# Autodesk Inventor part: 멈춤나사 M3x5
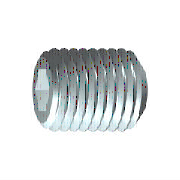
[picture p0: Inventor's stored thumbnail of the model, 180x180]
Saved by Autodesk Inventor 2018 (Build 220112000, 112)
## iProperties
Created: 2012-02
Part Number: 멈춤나사 M3x5
Material: 강철, 연강
Description: 6각 소켓 머리 없는 멈춤 나사
Document SubType Name: Modeling
Standard: KS B 1028
Designer: mduedu
Standards Organization: KS
Language: ko-KR
Size Designation: 납작점M3x5
Categories: <MemberInstance><Categories><Category DisplayName="조임쇠" InternalName="e4da775c-781d-43d5-af7c-5136215cf5a6" Mnemonic="FSTN"><Category DisplayName="볼트" InternalN
Density: 7.85 g/cm^3
Appearance: 노란색
Mass: 0.237365 g
Surface Area: 0.685518 cm^2
Volume: 0.0302376 cm^3
IsCustomPart: 1
Author: mduedu
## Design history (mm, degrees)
sketch "스케치1"
  geometry: L1 (0, 0)-(2.5, 0); L2 (5, 0.866)-(5, 1.5); L3 (5, 1.5)-(0, 1.5); L4 (5, 0.866)-(3, 0.866); L5 (3, 0.866)-(2.5, 0); L6 (0, -0.3)-(0, 1.8) reference; L7 (0, 1.5)-(0, 0)
  constraints: 13 end point, 3 parallel, 1 collinear, 1 perpendicular, 1 point on line
  dimensions: "d0" = 2 distance of L2.start L4.end (= INTI); "d1" = 60 deg angle of L5 L1; "d2" = 3 diameter of L3 L1 (= NND); "d3" = 1.73205 diameter of L4 L1 (= 1.1547 x SW); "d5" = 5 distance from line of L2 L3.end (= NLG)
revolve "본체" sketch "스케치1" stored, may be unused: angle "d6" = 90 deg
sketch "스케치2"
  geometry: L1 (-0.433, 0.75)-(0.433, 0.75); L2 (0.433, 0.75)-(0.866, 0); L3 (0.866, 0)-(0.433, -0.75); L4 (0.433, -0.75)-(-0.433, -0.75); L5 (-0.433, -0.75)-(-0.866, 0); L6 (-0.866, 0)-(-0.433, 0.75); A1 r 0.866 centre (0, 0) between (-0.433, 0.75) and (0.433, 0.75) reference; 2 further points
  constraints: 12 end point, 2 point on circle, 1 coincident, 1 horizontal, 11 other
extrude "슬롯" join sketch "스케치2" taper "d9" = 0 deg; stored distance "d21" = 10
workaxis "Work Axis1"
workplane "Work Plane1"
body "Solid1"
chamfer "모따기1" distance "d7" = 0.30673 (= -0.5 x GD1 + 0.5 x NND); stored, may be unused: angle "d8" = 45 deg (= FAWI), second distance "d29" = 0.30673 (= -0.5 x GD1 + 0.5 x NND)
feature "스레드" dims "d11" = 5 (= NLG), "d12" = 0
chamfer "모따기2" distance "d13" = 0.30673 (= -0.5 x GD1 + 0.5 x NND); stored, may be unused: angle "d14" = 45 deg (= FAWI), second distance "d30" = 0.30673 (= -0.5 x GD1 + 0.5 x NND)
other parameters: "NND" = 3 [user parameter; used in 5 equation terms], "NLG" = 5 [user parameter; used in 2 equation terms], "INTI" = 2 [user parameter; used in 1 equation term], "FAWI" = 45 deg [user parameter; used in 2 equation terms], "SW" = 1.5 [user parameter; used in 2 equation terms], "GD1" = 2.38655 (= THREADDIA - 1.2269 x PTC) [user parameter; used in 4 equation terms], "d4" = 0, "FAWI1" = 45 deg [user parameter], "d15" = 0, "d31" = 0, "GUL" = 0.30673 (= 0.61345 x PTC) [user parameter], "SPD" = 2 [user parameter], "TOA" = 30 deg [user parameter], "THREADDIA" = 3 [user parameter; used in 1 equation term], "PTC" = 0.5 [user parameter; used in 4 equation terms], "GAL" = 0.30673 (= 0.61345 x PTC) [user parameter], "E0" = 1.7325 (= 1.155 x SW) [user parameter]
